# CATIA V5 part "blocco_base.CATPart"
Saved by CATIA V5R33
Part number: blocco_base
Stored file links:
  C:\Users\Ryzen5700u\Desktop\robot_cicloidale_singolo\Assieme_robot_cicloidale_singolo\blocco_base.CATPart

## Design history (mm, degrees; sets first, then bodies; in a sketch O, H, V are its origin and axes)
Body1 "Solido1" (main body)
  Solid1: solid without history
